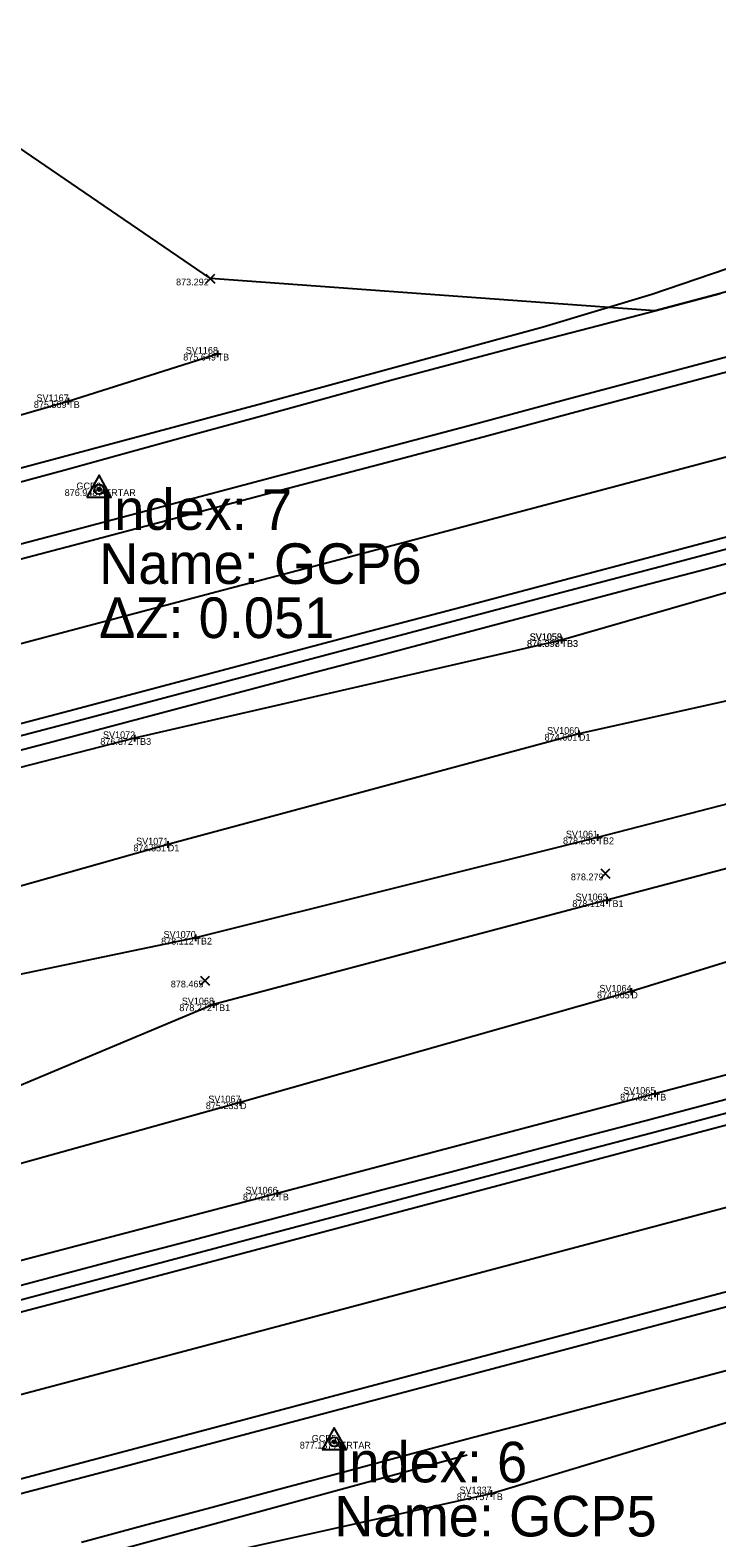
# Model space of a CAD drawing. Extents: x 2125299 to 2129212, y 713100 to 714300.
# Drawn here: x 2128416 to 2128517.6, y 713974 to 714196.9 of the extents above; entities that cross this region are included whole.
import ezdxf

# ---------------------------------------------------------------- set-up
doc = ezdxf.new("R2010")
doc.units = 0
for name, color, linetype in [('_CIVIL_CONSTRUCTION', 7, 'Continuous'), ('DR_X_Ditch', 7, 'Continuous'), ('DT_X_Terrain_Boundary', 7, 'Continuous'), ('PV_X_EOP', 7, 'Continuous'), ('PV_X_Shoulder_Rumble_Strip', 7, 'Continuous'), ('RW_P_Esmt_TMP', 7, 'Continuous'), ('RW_X_Esmt_CH', 7, 'Continuous'), ('RW_X_Fee_WL', 7, 'Continuous'), ('SC_Scratch1', 7, 'Continuous'), ('SC_Scratch2', 7, 'Continuous'), ('SV_P_Aerial_Targets', 7, 'Continuous'), ('SV_X_Mon_Cells_Found', 7, 'Continuous'), ('SV_X_Text_Elevation', 7, 'Continuous'), ('SV_X_Top_of_Bank', 7, 'Continuous')]:
    doc.layers.add(name, color=color, linetype=linetype)

msp = doc.modelspace()

# ---------------------------------------------------------------- linework, layer by layer
at = {"layer": '_CIVIL_CONSTRUCTION'}
for p, q in [((2128426.18, 714129.04), (2128426.18, 714129.04)), ((2128460.96, 713988.2), (2128460.96, 713988.2))]:
    msp.add_line(p, q, dxfattribs=at)
for points in [[(2128402.73, 714103.07), (2128417.23, 714106.91), (2128431.73, 714110.76), (2128446.23, 714114.6), (2128460.73, 714118.44), (2128475.23, 714122.28), (2128489.73, 714126.12), (2128504.23, 714129.96), (2128518.73, 714133.8), (2128533.23, 714137.64), (2128547.73, 714141.49), (2128562.23, 714145.33), (2128576.73, 714149.17), (2128591.23, 714153.01), (2128605.73, 714156.85), (2128620.23, 714160.69), (2128634.73, 714164.53), (2128649.23, 714168.37), (2128663.73, 714172.21)], [(2128413.82, 713995), (2128428.32, 713998.85), (2128442.82, 714002.69), (2128457.31, 714006.53), (2128471.81, 714010.37), (2128486.31, 714014.22), (2128500.81, 714018.06), (2128515.31, 714021.9), (2128529.81, 714025.74), (2128544.31, 714029.58), (2128558.81, 714033.42), (2128573.31, 714037.26), (2128587.81, 714041.1), (2128602.31, 714044.94), (2128616.82, 714048.77), (2128631.32, 714052.61), (2128645.82, 714056.45), (2128660.32, 714060.29)]]:
    msp.add_lwpolyline(points, dxfattribs=at)
for centre in [(2128426.18, 714129.04), (2128460.96, 713988.2)]:
    msp.add_circle(centre, 0.25, dxfattribs=at)
at = {"layer": 'DR_X_Ditch'}
for points in [[(2128525.29, 714099.16), (2128497.16, 714092.88), (2128436.33, 714076.51), (2128391.32, 714063.78), (2128330.37, 714048.18), (2128276.31, 714032.64)], [(2128539.96, 714065.48), (2128533.93, 714063.76), (2128504.91, 714054.76), (2128447.02, 714038.39), (2128399.37, 714025.09), (2128341.85, 714009.81), (2128283.6, 713994.68), (2128242.74, 713988.86), (2128205.78, 713990.56), (2128171.48, 713986), (2128143.07, 713980.05), (2128117.8, 713975.62)]]:
    msp.add_lwpolyline(points, dxfattribs=at)
at = {"layer": 'DT_X_Terrain_Boundary'}
msp.add_lwpolyline([(2128662.9, 714196.94), (2128653.22, 714194.42), (2128643.55, 714191.9), (2128633.87, 714189.39), (2128624.19, 714186.87), (2128614.52, 714184.32), (2128604.88, 714181.68), (2128595.23, 714179.04), (2128585.58, 714176.41), (2128575.94, 714173.77), (2128566.29, 714171.13), (2128556.64, 714168.5), (2128547, 714165.86), (2128537.35, 714163.22), (2128527.71, 714160.59), (2128518.05, 714157.98), (2128508.38, 714155.45), (2128442.63, 714160.2), (2128404.43, 714186.27)], dxfattribs=at)
at = {"layer": 'PV_X_EOP'}
for points in [[(2128411.83, 714129.41), (2128421.48, 714132.02), (2128431.12, 714134.67), (2128440.77, 714137.33), (2128450.41, 714139.98), (2128460.05, 714142.64), (2128469.69, 714145.3), (2128479.35, 714147.86), (2128489.03, 714150.39), (2128498.7, 714152.92), (2128508.38, 714155.45), (2128518.05, 714157.98)], [(2128409.73, 714089.22), (2128419.39, 714091.77), (2128429.06, 714094.32), (2128438.73, 714096.88), (2128448.4, 714099.43), (2128458.07, 714101.98), (2128467.74, 714104.54), (2128477.41, 714107.09), (2128487.07, 714109.64), (2128496.74, 714112.19), (2128506.41, 714114.75), (2128516.08, 714117.3), (2128525.73, 714119.91)], [(2128410.15, 714010.19), (2128419.82, 714012.74), (2128429.49, 714015.29), (2128439.16, 714017.84), (2128448.83, 714020.39), (2128458.5, 714022.94), (2128468.17, 714025.49), (2128477.84, 714028.04), (2128487.51, 714030.59), (2128497.18, 714033.13), (2128506.85, 714035.68), (2128516.52, 714038.23), (2128526.19, 714040.77)], [(2128423.59, 713973.35), (2128433.25, 713975.95), (2128442.91, 713978.54), (2128452.56, 713981.13), (2128462.22, 713983.72), (2128471.88, 713986.32), (2128481.55, 713988.87), (2128491.22, 713991.42), (2128500.89, 713993.97), (2128510.56, 713996.52), (2128520.23, 713999.07)]]:
    msp.add_lwpolyline(points, dxfattribs=at)
at = {"layer": 'PV_X_Shoulder_Rumble_Strip'}
for points in [[(2128408.92, 714119.5), (2128423.43, 714123.32), (2128437.93, 714127.15), (2128452.44, 714130.97), (2128466.94, 714134.8), (2128481.44, 714138.64), (2128495.93, 714142.5), (2128510.43, 714146.36), (2128524.93, 714150.21), (2128539.42, 714154.07), (2128553.92, 714157.93), (2128568.41, 714161.78), (2128582.91, 714165.64), (2128597.41, 714169.49), (2128611.9, 714173.35), (2128626.4, 714177.21), (2128640.89, 714181.06), (2128655.39, 714184.92)], [(2128407.66, 714090.8), (2128422.17, 714094.63), (2128436.67, 714098.47), (2128451.17, 714102.3), (2128465.67, 714106.14), (2128480.17, 714109.97), (2128494.67, 714113.81), (2128509.17, 714117.64), (2128523.68, 714121.48), (2128538.18, 714125.32), (2128552.68, 714129.15), (2128567.18, 714132.99), (2128581.68, 714136.82), (2128596.18, 714140.66), (2128610.68, 714144.49), (2128625.19, 714148.33), (2128639.69, 714152.15), (2128654.19, 714155.98), (2128668.69, 714159.81)], [(2128406.18, 714006.98), (2128420.68, 714010.82), (2128435.18, 714014.66), (2128449.68, 714018.5), (2128464.18, 714022.34), (2128478.68, 714026.18), (2128493.18, 714030.02), (2128507.68, 714033.86), (2128522.18, 714037.69), (2128536.68, 714041.53), (2128551.18, 714045.37), (2128565.68, 714049.2), (2128580.18, 714053.04), (2128594.68, 714056.88), (2128609.19, 714060.72), (2128623.69, 714064.55), (2128638.19, 714068.39), (2128652.69, 714072.23), (2128667.19, 714076.06)], [(2128413.44, 713980.24), (2128427.94, 713984.07), (2128442.44, 713987.91), (2128456.94, 713991.75), (2128471.44, 713995.6), (2128485.94, 713999.44), (2128500.44, 714003.29), (2128514.94, 714007.13), (2128529.44, 714010.97), (2128543.94, 714014.82), (2128558.44, 714018.66), (2128572.93, 714022.51), (2128587.43, 714026.35), (2128601.93, 714030.2), (2128616.43, 714034.04), (2128630.93, 714037.88), (2128645.43, 714041.73), (2128659.93, 714045.57)]]:
    msp.add_lwpolyline(points, dxfattribs=at)
at = {"layer": 'SC_Scratch1'}
for points in [[(2128628.95, 714194.22), (2128585.4, 714182.79), (2128564.12, 714177.04), (2128556.66, 714174.91), (2128549.07, 714172.15), (2128542.5, 714169.81), (2128530.23, 714165.43), (2128519.08, 714161.63), (2128507.97, 714157.87), (2128491.85, 714153.02), (2128450.41, 714141.74), (2128284.96, 714097.53), (2128098.63, 714048.44)], [(2128073.34, 713879.42), (2128205.29, 713913.45), (2128375.42, 713957.63), (2128480.61, 713986.26)]]:
    msp.add_lwpolyline(points, dxfattribs=at)
at = {"layer": 'SC_Scratch2'}
for points in [[(2128409.71, 714117.48), (2128424.21, 714121.3), (2128438.72, 714125.13), (2128453.22, 714128.95), (2128467.73, 714132.78), (2128482.23, 714136.62), (2128496.72, 714140.48), (2128511.22, 714144.33), (2128525.71, 714148.19), (2128540.21, 714152.05), (2128554.7, 714155.9), (2128569.2, 714159.76), (2128583.7, 714163.62), (2128598.19, 714167.47), (2128612.69, 714171.33), (2128627.18, 714175.19), (2128641.68, 714179.04), (2128656.18, 714182.9)], [(2128407.2, 714092.47), (2128421.7, 714096.3), (2128436.2, 714100.14), (2128450.7, 714103.97), (2128465.2, 714107.81), (2128479.7, 714111.64), (2128494.21, 714115.48), (2128508.71, 714119.31), (2128523.21, 714123.15), (2128537.71, 714126.98), (2128552.21, 714130.82), (2128566.71, 714134.66), (2128581.21, 714138.49), (2128595.72, 714142.33), (2128610.22, 714146.16), (2128624.72, 714150), (2128639.22, 714153.82), (2128653.73, 714157.65), (2128668.23, 714161.48)], [(2128407.09, 714005.42), (2128421.59, 714009.26), (2128436.09, 714013.1), (2128450.59, 714016.94), (2128465.09, 714020.78), (2128479.59, 714024.62), (2128494.09, 714028.45), (2128508.59, 714032.29), (2128523.09, 714036.13), (2128537.59, 714039.96), (2128552.09, 714043.8), (2128566.59, 714047.64), (2128581.09, 714051.48), (2128595.59, 714055.31), (2128610.09, 714059.15), (2128624.6, 714062.99), (2128639.1, 714066.82), (2128653.6, 714070.66), (2128668.1, 714074.5)], [(2128413.06, 713982.34), (2128427.56, 713986.17), (2128442.06, 713990), (2128456.56, 713993.85), (2128471.06, 713997.69), (2128485.56, 714001.53), (2128500.06, 714005.38), (2128514.56, 714009.22), (2128529.06, 714013.07), (2128543.56, 714016.91), (2128558.06, 714020.76), (2128572.55, 714024.6), (2128587.05, 714028.45), (2128601.55, 714032.29), (2128616.05, 714036.13), (2128630.55, 714039.98), (2128645.05, 714043.82), (2128659.55, 714047.67)]]:
    msp.add_lwpolyline(points, dxfattribs=at)
at = {"layer": 'SV_P_Aerial_Targets'}
for p, q in [((2128426.18, 714129.04), (2128426.18, 714129.04)), ((2128460.96, 713988.2), (2128460.96, 713988.2))]:
    msp.add_line(p, q, dxfattribs=at)
for points in [[(2128424.38, 714127.89), (2128427.98, 714127.89), (2128426.18, 714131.11)], [(2128424.38, 714127.89), (2128427.98, 714127.89), (2128426.18, 714131.11)], [(2128459.16, 713987.05), (2128462.76, 713987.05), (2128460.96, 713990.27)], [(2128459.16, 713987.05), (2128462.76, 713987.05), (2128460.96, 713990.27)]]:
    msp.add_lwpolyline(points, close=True, dxfattribs=at)
for centre, radius in [((2128426.18, 714129.04), 0.7), ((2128426.18, 714129.04), 0.7), ((2128426.18, 714129.04), 0.16), ((2128426.18, 714129.04), 0.16), ((2128460.96, 713988.2), 0.7), ((2128460.96, 713988.2), 0.7), ((2128460.96, 713988.2), 0.16), ((2128460.96, 713988.2), 0.16)]:
    msp.add_circle(centre, radius, dxfattribs=at)
at = {"layer": 'SV_X_Mon_Cells_Found'}
for p, q in [((2128443.2, 714149.09), (2128444.2, 714149.09)), ((2128443.7, 714149.59), (2128443.7, 714148.59)), ((2128443.7, 714149.09), (2128443.7, 714149.09)), ((2128421.1, 714142.07), (2128422.1, 714142.07)), ((2128421.6, 714142.57), (2128421.6, 714141.57)), ((2128421.6, 714142.07), (2128421.6, 714142.07)), ((2128494.06, 714106.73), (2128495.06, 714106.73)), ((2128494.09, 714106.74), (2128495.09, 714106.74)), ((2128494.56, 714107.23), (2128494.56, 714106.23)), ((2128494.56, 714106.73), (2128494.56, 714106.73)), ((2128494.59, 714107.24), (2128494.59, 714106.24)), ((2128494.59, 714106.74), (2128494.59, 714106.74)), ((2128430.92, 714092.25), (2128431.92, 714092.25)), ((2128431.42, 714092.75), (2128431.42, 714091.75)), ((2128431.42, 714092.25), (2128431.42, 714092.25)), ((2128496.66, 714092.88), (2128497.66, 714092.88)), ((2128497.16, 714093.38), (2128497.16, 714092.38)), ((2128497.16, 714092.88), (2128497.16, 714092.88)), ((2128435.83, 714076.51), (2128436.83, 714076.51)), ((2128436.33, 714077.01), (2128436.33, 714076.01)), ((2128436.33, 714076.51), (2128436.33, 714076.51)), ((2128499.4, 714077.56), (2128500.4, 714077.56)), ((2128499.9, 714078.06), (2128499.9, 714077.06)), ((2128499.9, 714077.56), (2128499.9, 714077.56)), ((2128500.81, 714068.27), (2128501.81, 714068.27)), ((2128501.31, 714068.77), (2128501.31, 714067.77)), ((2128501.31, 714068.27), (2128501.31, 714068.27)), ((2128440.42, 714063.23), (2128440.42, 714062.23)), ((2128439.92, 714062.73), (2128440.92, 714062.73)), ((2128440.42, 714062.73), (2128440.42, 714062.73)), ((2128504.41, 714054.76), (2128505.41, 714054.76)), ((2128504.91, 714055.26), (2128504.91, 714054.26)), ((2128504.91, 714054.76), (2128504.91, 714054.76)), ((2128442.61, 714052.88), (2128443.61, 714052.88)), ((2128443.11, 714053.38), (2128443.11, 714052.38)), ((2128443.11, 714052.88), (2128443.11, 714052.88)), ((2128446.52, 714038.39), (2128447.52, 714038.39)), ((2128447.02, 714038.89), (2128447.02, 714037.89)), ((2128447.02, 714038.39), (2128447.02, 714038.39)), ((2128507.87, 714039.66), (2128508.87, 714039.66)), ((2128508.37, 714040.16), (2128508.37, 714039.16)), ((2128508.37, 714039.66), (2128508.37, 714039.66)), ((2128452.53, 714025.4), (2128452.53, 714024.4)), ((2128452.03, 714024.9), (2128453.03, 714024.9)), ((2128452.53, 714024.9), (2128452.53, 714024.9)), ((2128483.69, 713980.57), (2128484.69, 713980.57)), ((2128484.19, 713981.07), (2128484.19, 713980.07)), ((2128484.19, 713980.57), (2128484.19, 713980.57))]:
    msp.add_line(p, q, dxfattribs=at)
at = {"layer": 'SV_X_Text_Elevation'}
for p, q in [((2128441.96, 714159.53), (2128443.3, 714160.87)), ((2128441.96, 714160.87), (2128443.3, 714159.53)), ((2128500.39, 714071.56), (2128501.72, 714072.9)), ((2128500.39, 714072.9), (2128501.72, 714071.56)), ((2128441.19, 714055.72), (2128442.52, 714057.06)), ((2128441.19, 714057.06), (2128442.52, 714055.72))]:
    msp.add_line(p, q, dxfattribs=at)
at = {"layer": 'SV_X_Top_of_Bank'}
for points in [[(2128105.46, 714054.71), (2128114.11, 714060.74), (2128124.65, 714063.56), (2128152.61, 714070.67), (2128179.16, 714077.14), (2128212.09, 714085.22), (2128215.23, 714083.5), (2128232.87, 714085.47), (2128251.15, 714091.35), (2128260.26, 714099.99), (2128265.91, 714101.36), (2128273.54, 714100.32), (2128289.09, 714106.73), (2128315.22, 714112.36), (2128351.86, 714121.53), (2128391.6, 714133.45), (2128421.6, 714142.07), (2128443.7, 714149.09)], [(2128621.75, 714139.89), (2128575.4, 714127.43), (2128536.54, 714118.82), (2128494.56, 714106.73), (2128494.59, 714106.74), (2128431.42, 714092.25), (2128387.26, 714080.92), (2128325.7, 714062.91), (2128270.25, 714048.29), (2128232.44, 714039), (2128192.57, 714028.85), (2128120.54, 714010.42)], [(2128630.23, 714112.45), (2128582.67, 714099.87), (2128543.67, 714088.86), (2128499.9, 714077.56), (2128440.42, 714062.73), (2128393.57, 714052.94), (2128334.24, 714034.3), (2128278.14, 714020.98), (2128236.99, 714017.4), (2128194.11, 714013.25), (2128178.62, 714010.69), (2128139.13, 714003.23), (2128093.27, 713996.96)], [(2128632.64, 714103.31), (2128584.74, 714089.99), (2128545.97, 714080.06), (2128501.31, 714068.27), (2128443.11, 714052.88), (2128397.55, 714033.79), (2128338.65, 714020.42), (2128280.89, 714002.86), (2128241.69, 713997.86), (2128197.7, 714003.21), (2128178.62, 714010.69)], [(2128641.06, 714074.44), (2128591.12, 714062.19), (2128554.7, 714051.88), (2128508.37, 714039.66), (2128452.53, 714024.9), (2128402.4, 714011.79), (2128346.92, 713996.07), (2128287.48, 713981.18), (2128247.17, 713969.96), (2128213.74, 713962.2), (2128176.95, 713953.14), (2128149.75, 713946.28), (2128088.07, 713932.71), (2128089.34, 713952.15), (2128089.79, 713973.52), (2128093.27, 713996.96)], [(2128074.37, 713874.69), (2128142.8, 713890.6), (2128198.94, 713905.19), (2128254.99, 713920.63), (2128306.24, 713935.17), (2128365.05, 713950.7), (2128425.17, 713967.42), (2128484.19, 713980.57), (2128536.73, 713996.44), (2128593.25, 714009.66)]]:
    msp.add_lwpolyline(points, dxfattribs=at)

# ---------------------------------------------------------------- texts
at = {"layer": '_CIVIL_CONSTRUCTION'}
for s, p in [('Index: 7', (2128426.18, 714123.05)), ('Name: GCP6', (2128426.18, 714115.05)), ('ΔZ: 0.051', (2128426.18, 714107.05)), ('Index: 6', (2128460.96, 713982.2)), ('Name: GCP5', (2128460.96, 713974.2))]:
    msp.add_text(s, height=6, dxfattribs=at).set_placement(p)
at = {"layer": 'RW_P_Esmt_TMP'}
for s, p in [('TB', (2128443.7, 714148.09)), ('TB', (2128421.6, 714141.07)), ('AERTAR', (2128426.18, 714128.05)), ('AERTAR', (2128426.18, 714128.05)), ('TB3', (2128494.56, 714105.73)), ('TB3', (2128494.59, 714105.74)), ('TB3', (2128431.42, 714091.25)), ('D1', (2128497.16, 714091.88)), ('D1', (2128436.33, 714075.51)), ('TB2', (2128499.9, 714076.56)), ('TB1', (2128501.31, 714067.27)), ('TB2', (2128440.42, 714061.73)), ('D', (2128504.91, 714053.76)), ('TB1', (2128443.11, 714051.88)), ('D', (2128447.02, 714037.39)), ('TB', (2128508.37, 714038.66)), ('TB', (2128452.53, 714023.9)), ('AERTAR', (2128460.96, 713987.2)), ('AERTAR', (2128460.96, 713987.2)), ('TB', (2128484.19, 713979.57))]:
    msp.add_text(s, height=1, dxfattribs=at).set_placement(p)
at = {"layer": 'RW_X_Esmt_CH'}
for s, p in [('SV1168', (2128439, 714149.09)), ('SV1167', (2128416.91, 714142.07)), ('GCP6', (2128422.82, 714129.04)), ('GCP6', (2128422.82, 714129.04)), ('SV1058', (2128489.86, 714106.73)), ('SV1059', (2128489.91, 714106.74)), ('SV1072', (2128426.75, 714092.25)), ('SV1060', (2128492.45, 714092.88)), ('SV1061', (2128495.23, 714077.56)), ('SV1071', (2128431.65, 714076.51)), ('SV1063', (2128496.65, 714068.27)), ('SV1070', (2128435.71, 714062.73)), ('SV1068', (2128438.41, 714052.88)), ('SV1064', (2128500.19, 714054.76)), ('SV1065', (2128503.7, 714039.66)), ('SV1067', (2128442.33, 714038.39)), ('SV1066', (2128447.83, 714024.9)), ('GCP5', (2128457.63, 713988.2)), ('GCP5', (2128457.63, 713988.2)), ('SV1337', (2128479.49, 713980.57))]:
    msp.add_text(s, height=1, dxfattribs=at).set_placement(p)
at = {"layer": 'RW_X_Fee_WL'}
for s, p in [('873.292', (2128437.56, 714159.2)), ('875.649', (2128438.62, 714148.09)), ('875.569', (2128416.52, 714141.07)), ('876.948', (2128421.08, 714128.05)), ('876.948', (2128421.08, 714128.05)), ('876.397', (2128489.46, 714105.73)), ('876.398', (2128489.49, 714105.74)), ('876.872', (2128426.35, 714091.25)), ('874.601', (2128492.08, 714091.88)), ('874.851', (2128431.25, 714075.51)), ('878.256', (2128494.8, 714076.56)), ('878.279', (2128495.97, 714071.23)), ('878.114', (2128496.18, 714067.27)), ('878.112', (2128435.35, 714061.73)), ('878.465', (2128436.78, 714055.39)), ('874.965', (2128499.84, 714053.76)), ('878.272', (2128438.04, 714051.88)), ('875.233', (2128441.96, 714037.39)), ('877.024', (2128503.25, 714038.66)), ('877.212', (2128447.45, 714023.9)), ('877.137', (2128455.86, 713987.2)), ('877.137', (2128455.86, 713987.2)), ('875.757', (2128479.09, 713979.57))]:
    msp.add_text(s, height=1, dxfattribs=at).set_placement(p)

doc.saveas('drawing.dxf')
